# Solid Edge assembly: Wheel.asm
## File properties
Title: Wheel Subassembly
Subject: Trolley Wheel Assembly
Author: kiyo
Keywords: Subassembly
Comments: Wheel Subassembly
Template: metric.asm
Last saved by: edge
Revision: 36
Application: Solid Edge
Category: Subassembly
Manager: Brian Little
Company: Wheels R Us
File Size: 0
Number of Sheets: 0
Number of Objects: 0
Username: kiyo
文書内容のタイプ: 1
Document Number: WSA-202
Revision: 1
Project Name: Trolley Wheel Assembly
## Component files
Axle.par
bearing.par
sraxle.par
wheel.par
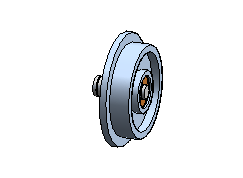
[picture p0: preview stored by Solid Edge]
